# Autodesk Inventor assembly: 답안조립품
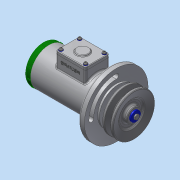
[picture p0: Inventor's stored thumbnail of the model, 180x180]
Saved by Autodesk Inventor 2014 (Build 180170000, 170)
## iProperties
Created: 2017-05
Part Number: 답안조립품
Document SubType Name: Assembly
Designer: SCD-A15
Author: SCD-A15
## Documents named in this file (20)
- C:\Users\SCD-A15\Desktop\470508V1021\답안조립품.iam
- C:\Users\SCD-A15\Desktop\470508V1021\본체.ipt
- C:\Users\SCD-A15\Desktop\470508V1021\V-벨트풀리.ipt
- C:\Users\SCD-A15\Desktop\470508V1021\너트 M10.ipt
- C:\Users\SCD-A15\Desktop\470508V1021\멈춤링 15 x 1.ipt
- C:\Users\SCD-A15\Desktop\470508V1021\멈춤링 35x1.6.ipt
- C:\Users\SCD-A15\Desktop\470508V1021\베어링 15 x 35 x 11.ipt
- C:\Users\SCD-A15\Desktop\470508V1021\볼트 M4 x 10.ipt
- C:\Users\SCD-A15\Desktop\470508V1021\부시1.ipt
- C:\Users\SCD-A15\Desktop\470508V1021\부시2.ipt
- C:\Users\SCD-A15\Desktop\470508V1021\사이드 커버.ipt
- 사이드 커버.ipt
- C:\Users\SCD-A15\Desktop\470508V1021\십자볼트 M3 x 10.ipt
- C:\Users\SCD-A15\Desktop\470508V1021\오일 실 15 25 7.ipt
- C:\Users\SCD-A15\Desktop\470508V1021\와셔 3x6.ipt
- C:\Users\SCD-A15\Desktop\470508V1021\와셔 4x16.ipt
- C:\Users\SCD-A15\Desktop\470508V1021\와셔 10x21.ipt
- C:\Users\SCD-A15\Desktop\470508V1021\축.ipt
- C:\Users\SCD-A15\Desktop\470508V1021\키 4 x 4 x 18.ipt
- C:\Users\SCD-A15\Desktop\470508V1021\탑 커버.ipt
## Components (2 placed, 2 different names)
1. V-벨트풀리:1 — 각도:1
2. ISO 4017 M4 x 10:1
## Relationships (1: Angle 1)
- 각도:1 [Angle]: V-벨트풀리:1
## Named parameters: d16_d15 = 0, d17_d15 = 0, d18_d15 = 0
